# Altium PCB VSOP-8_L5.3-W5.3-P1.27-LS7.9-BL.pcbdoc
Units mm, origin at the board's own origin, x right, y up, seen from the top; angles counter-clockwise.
Board outline 18.06 x 21.8 mm, 2 copper layers (Top Layer, Bottom Layer), stack 0 mm thick; 1 components, 0 nets, 8 pads, 0 vias.
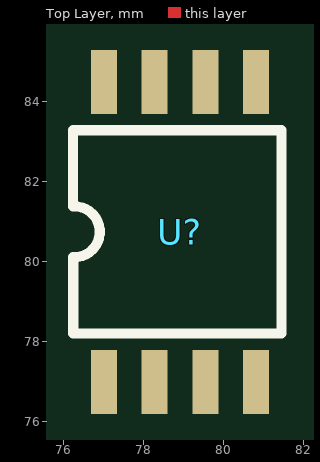
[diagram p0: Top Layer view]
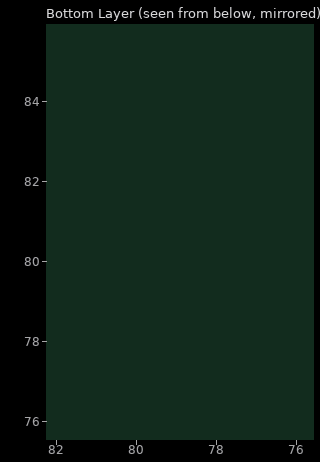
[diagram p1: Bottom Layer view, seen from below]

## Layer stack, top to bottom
Top Layer: signal copper (thickness not stored)
Bottom Layer: signal copper (thickness not stored)

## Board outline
87.91,69.85 69.85,69.85 69.85,91.65 87.91,91.65

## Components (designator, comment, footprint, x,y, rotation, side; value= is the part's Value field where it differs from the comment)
U? "" VSOP-8_L5.3-W5.3-P1.27-LS7.9-BL 78.91,80.75 r0 top

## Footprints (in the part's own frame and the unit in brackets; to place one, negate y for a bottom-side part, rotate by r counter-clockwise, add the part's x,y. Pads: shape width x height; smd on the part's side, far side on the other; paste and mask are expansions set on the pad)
VSOP-8_L5.3-W5.3-P1.27-LS7.9-BL [mm]
  rect 0.65x1.6 smd: 1(-1.905,-3.75) 2(-0.635,-3.75) 3(0.635,-3.75) 4(1.905,-3.75) 5(1.905,3.75) 6(0.635,3.75) 7(-0.635,3.75) 8(-1.905,3.75)
  silkscreen extent -2.67,-2.54 2.54,2.54

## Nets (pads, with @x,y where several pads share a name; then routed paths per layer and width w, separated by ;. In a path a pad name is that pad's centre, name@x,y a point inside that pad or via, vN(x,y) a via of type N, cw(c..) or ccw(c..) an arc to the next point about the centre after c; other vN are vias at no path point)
pads on no net: U?.1 U?.2 U?.3 U?.4 U?.5 U?.6 U?.7 U?.8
